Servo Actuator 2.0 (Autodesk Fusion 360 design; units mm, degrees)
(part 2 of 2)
sketch "Sketch25" plane through (0, 0, 1.008) normal (0, 0, 1) x axis (-1, 0, 0)
  line L1 (-20.0076, 9.3042) -> (-16.55, 9.3042)
  line L2 (-20.0076, 2.9542) -> (-20.0076, 9.3042)
  line L3 (-16.55, 2.9542) -> (-20.0076, 2.9542)
  line L4 (-20.0076, -11.4458) -> (-17.255, -11.4458)
  line L5 (-20.0076, -17.7958) -> (-20.0076, -11.4458)
  line L6 (-17.255, -17.7958) -> (-20.0076, -17.7958)
  line L7 (-3.4928, -22.1208) -> (-13.668, -22.1208)
  line L8 (0.1537, -18.4744) -> (-3.4928, -22.1208)
  line L9 (0.1537, -10.7673) -> (0.1537, -18.4744)
  line L10 (-3.4928, -7.1208) -> (0.1537, -10.7673)
  line L11 (-13.668, -7.1208) -> (-3.4928, -7.1208)
  line L12 (-20.0076, -17.7958) -> (-17.255, -17.7958)
  line L13 (-20.0076, -11.4458) -> (-20.0076, -17.7958)
  line L14 (-17.255, -11.4458) -> (-20.0076, -11.4458)
  line L15 (-17.255, -17.7958) -> (-17.255, -11.4458)
  line L16 (-20.0076, 2.9542) -> (-16.55, 2.9542)
  line L17 (-20.0076, 9.3042) -> (-20.0076, 2.9542)
  line L18 (-16.55, 9.3042) -> (-20.0076, 9.3042)
  line L19 (-16.55, 2.9542) -> (-16.55, 9.3042)
  arc A1 centre (-8.3963, 6.1292) radius 8.75 clockwise from (-16.55, 9.3042) to (-16.55, 2.9542)
  arc A2 centre (-9.026, -14.6208) radius 8.8203 clockwise from (-17.255, -11.4458) to (-13.668, -7.1208)
  arc A3 centre (-9.026, -14.6208) radius 8.8203 clockwise from (-13.668, -22.1208) to (-17.255, -17.7958)
  point P10 (-20.0076, -11.4458)
  point P20 (-20.0076, -11.4458)
  point P12 (-17.255, -17.7958)
  point P18 (-17.255, -17.7958)
  point P5 (-20.0076, 9.3042)
  point P24 (-20.0076, 9.3042)
  point P2 (-16.55, 2.9542)
  point P22 (-16.55, 2.9542)
  horizontal L12
  vertical L13
  horizontal L14
  vertical L15
  coincident P10 P20
  coincident P12 P18
  horizontal L16
  vertical L17
  horizontal L18
  vertical L19
  coincident P5 P24
  coincident P2 P22
extrude "Extrude10" cut sketch "Sketch25" profile of L1 L2 L3 L16 L17 L18 L19 against normal blind 8.89
extrude "Extrude11" cut sketch "Sketch25" profile of L4 L5 L6 L12 L13 L14 L15 distance 11.43
copy_paste "CutPaste1"
remove_instance "RemoveInstance8"
sketch "Sketch1" plane through (0, 0, 0) normal (0, 0, 1) x axis (1, 0, 0)
  line L1 (-7.25, -8.75) -> (7.25, -8.75)
  line L2 (-7.25, 8.75) -> (-7.25, -8.75)
  line L3 (7.25, 8.75) -> (-7.25, 8.75)
  line L4 (7.25, -8.75) -> (7.25, 8.75)
  line L5 (-7.25, 8.75) -> (7.25, -8.75)
  line L6 (7.25, 8.75) -> (-7.25, -8.75)
  line L7 (0, 8.75) -> (0, -8.75)
  line L8 (-2.5, -2.35) -> (2.5, -2.35)
  line L9 (-2.5, 1.45) -> (-2.5, -2.35)
  line L10 (2.5, 1.45) -> (-2.5, 1.45)
  line L11 (2.5, -2.35) -> (2.5, 1.45)
  line L12 (-2.5, 1.45) -> (2.5, -2.35)
  line L13 (2.5, 1.45) -> (-2.5, -2.35)
  line L14 (7.25, -0.45) -> (-7.25, -0.45)
  line L15 (3.75, -8.75) -> (7.25, -5.25)
  line L16 (-3.75, -8.75) -> (-7.25, -5.25)
  arc A1 centre (0, 0.1797) radius 8.5703 clockwise from (-7.25, 4.75) to (7.25, 4.75)
  circle C1 centre (6, -0.45) radius 1.5
  circle C2 centre (-6, -0.45) radius 1.5
  point P6 (0, 0)
  point P1 (0, 0)
  point P7 (0, -8.75)
  point P8 (0, 8.75)
  point P13 (0, -0.45)
  point P14 (-7.25, -0.45)
  point P15 (7.25, -0.45)
  point P16 (7.25, 4.75)
  point P17 (-7.25, 4.75)
  point P19 (7.25, 4.75)
  point P18 (-7.25, 4.75)
  point P21 (7.25, -5.25)
  point P22 (3.75, -8.75)
  point P23 (7.25, -5.25)
  point P24 (3.75, -8.75)
  point P25 (-7.25, -5.25)
  point P26 (-3.75, -8.75)
  point P27 (6, -0.45)
  point P2 (7.25, -8.75)
  point P5 (7.25, 8.75)
  horizontal L1
  perpendicular L1 L2
  parallel L1 L3
  parallel L2 L4
  coincident L5 P6
  coincident L6 P6
  coincident P1 P6
  midpoint L1 P7
  midpoint L3 P8
  horizontal L8
  perpendicular L8 L9
  parallel L8 L10
  parallel L9 L11
  coincident L12 P13
  coincident L13 P13
  coincident L7 P13
  coincident L2 P14
  coincident L4 P15
  perpendicular L4 L14
  coincident P13 L14
  coincident L4 P16
  symmetric L7 P16 P17
  coincident P8 A1
  tangent L3 A1
  coincident P16 P19
  coincident P17 P18
  coincident L4 P21
  coincident L1 P22
  coincident P21 P23
  coincident P22 P24
  symmetric L7 P23 P25
  symmetric L7 P24 P26
  coincident L14 P27
  symmetric L7 C1 C2
  dimension "d1_4" distance P2 P5 = 17.5
  dimension "d2_4" distance L2 L4 = 14.5
  dimension "d3_4" distance L1 L8 = 6.4
  dimension "d4_4" distance L3 L10 = 7.3
  dimension "d5_4" distance L9 L11 = 5
  dimension "d6_4" distance P5 P16 = 4
  dimension "d7_4" distance P2 P21 = 3.5
  dimension "d8_4" distance P2 P22 = 3.5
  dimension "d9_4" diameter C1 = 3
  dimension "d10_4" distance L11 P27 = 3.5 (= "2 mm + 1.5 mm")
extrude "Extrude1" new body sketch "Sketch1" profile of L1 L2 L4 L8 L9 L10 L11 A1 L15 L16 C1 C2 against normal blind 1.7 named "d11_4"
extrude "Extrude2" new body sketch "Sketch1" profile of L8 L9 L10 L11 along normal blind 1.5 named "d13_4"
sketch "Sketch2" plane through (0, 0, 0) normal (0, 0, 1) x axis (-1, 0, 0)
  line L1 (3.75, 8.75) -> (7.25, 5.25)
  line L2 (-3.75, 8.75) -> (3.75, 8.75)
  line L3 (-7.25, 5.25) -> (-3.75, 8.75)
  line L4 (-7.25, 1.2792) -> (-7.25, 5.25)
  line L5 (-7.25, -4.75) -> (-7.25, -0.3792)
  line L6 (7.25, -0.3792) -> (7.25, -4.75)
  line L7 (7.25, 5.25) -> (7.25, 1.2792)
  line L8 (2.5, -1.45) -> (-2.5, -1.45)
  line L9 (2.5, 2.35) -> (2.5, -1.45)
  line L10 (-2.5, 2.35) -> (2.5, 2.35)
  line L11 (-2.5, -1.45) -> (-2.5, 2.35)
  line L12 (2.5, 2.35) -> (-2.5, -1.45)
  line L13 (2.5, -1.45) -> (-2.5, 2.35)
  line L14 (11.5, 11.95) -> (-11.5, 11.95)
  line L15 (11.5, -11.05) -> (11.5, 11.95)
  line L16 (-11.5, -11.05) -> (11.5, -11.05)
  line L17 (-11.5, 11.95) -> (-11.5, -11.05)
  line L18 (11.5, -11.05) -> (-11.5, 11.95)
  line L19 (-11.5, -11.05) -> (11.5, 11.95)
  line L20 (8.5, 8.95) -> (-8.5, 8.95)
  line L21 (8.5, -8.05) -> (8.5, 8.95)
  line L22 (-8.5, -8.05) -> (8.5, -8.05)
  line L23 (-8.5, 8.95) -> (-8.5, -8.05)
  line L24 (8.5, -8.05) -> (-8.5, 8.95)
  line L25 (-8.5, -8.05) -> (8.5, 8.95)
  arc A1 centre (-6, 0.45) radius 1.5 clockwise from (-7.25, 1.2792) to (-7.25, -0.3792)
  arc A2 centre (0, -0.1797) radius 8.5703 clockwise from (7.25, -4.75) to (-7.25, -4.75)
  arc A3 centre (6, 0.45) radius 1.5 clockwise from (7.25, -0.3792) to (7.25, 1.2792)
  circle C1 centre (-8.5, 8.95) radius 1.5
  point P15 (-2.5, -1.45)
  point P19 (-2.5, -1.45)
  point P17 (2.5, 2.35)
  point P20 (2.5, 2.35)
  point P18 (-2.5, 2.35)
  point P21 (-2.5, 2.35)
  point P16 (2.5, -1.45)
  point P22 (2.5, -1.45)
  point P27 (0, 0.45)
  point P32 (0, 0.45)
  point P28 (-8.5, 8.95)
  point P33 (-8.5, 8.95)
  point P25 (11.5, -11.05)
  point P26 (-11.5, -11.05)
  point P24 (11.5, 11.95)
  point P29 (8.5, 8.95)
  point P31 (-8.5, -8.05)
  coincident P15 P19
  coincident P17 P20
  coincident P18 P21
  coincident P16 P22
  horizontal L14
  perpendicular L14 L15
  parallel L14 L16
  parallel L15 L17
  coincident L18 P27
  coincident L19 P27
  midpoint L12 P27
  horizontal L20
  perpendicular L20 L21
  parallel L20 L22
  parallel L21 L23
  coincident L24 P32
  coincident L25 P32
  coincident P27 P32
  coincident P28 P33
  dimension "d15_3" distance P25 P26 = 23
  dimension "d16_3" distance P24 P25 = 23
  dimension "d21_3" distance P28 P29 = 17
  dimension "d22_1" distance P28 P31 = 17
  dimension "d23_1" diameter C1 = 3
extrude "Extrude3" add sketch "Sketch2" profile of L1 L2 L3 L4 A1 L5 A2 L6 A3 L7 L8 L9 L10 L11 L14 L15 L16 L17 against normal blind 1.7 named "d17_3"
fillet "Fillet1" radius 3 named "d20_3"
extrude "Extrude4" cut sketch "Sketch2" profile of C1 against normal blind 5 named "d24_1"
work_axis "WorkAxis1" sketch "Sketch2"
circular_pattern "C-Pattern1" TotalAngle 360 named "d27_1"
copy_paste "CutPaste7"
copy_paste_bodies "CopyPasteBodies1"
component_from_bodies "Body->Comp2"
copy_paste "CutPaste1"
sketch "Sketch26" plane through (0, 0, 3.1168) normal (0, 0, 1) x axis (-1, 0, 0)
  line L1 (-17.255, -17.7958) -> (-17.255, -11.4458)
  line L2 (-3.4928, -22.1208) -> (-13.668, -22.1208)
  line L3 (0.1537, -18.4744) -> (-3.4928, -22.1208)
  line L4 (0.1537, -10.7673) -> (0.1537, -18.4744)
  line L5 (-3.4928, -7.1208) -> (0.1537, -10.7673)
  line L6 (-13.668, -7.1208) -> (-3.4928, -7.1208)
  line L7 (-10.2963, -17.1208) -> (-10.2963, -12.1208)
  line L8 (-6.4963, -17.1208) -> (-10.2963, -17.1208)
  line L9 (-6.4963, -12.1208) -> (-6.4963, -17.1208)
  line L10 (-10.2963, -12.1208) -> (-6.4963, -12.1208)
  line L11 (-6.4963, -12.1208) -> (-10.2963, -17.1208)
  line L12 (-10.2963, -12.1208) -> (-6.4963, -17.1208)
  line L13 (6.8437, -26.1208) -> (-23.6363, -26.1208)
  line L14 (6.8437, -3.1208) -> (6.8437, -26.1208)
  line L15 (-23.6363, -3.1208) -> (6.8437, -3.1208)
  line L16 (-23.6363, -26.1208) -> (-23.6363, -3.1208)
  line L17 (6.8437, -3.1208) -> (-23.6363, -26.1208)
  line L18 (-23.6363, -3.1208) -> (6.8437, -26.1208)
  line L19 (-23.8863, -26.3708) -> (-23.8863, -2.8708)
  line L20 (7.0937, -26.3708) -> (-23.8863, -26.3708)
  line L21 (7.0937, -2.8708) -> (7.0937, -26.3708)
  line L22 (-23.8863, -2.8708) -> (7.0937, -2.8708)
  line L23 (-3.6338, -9.3883) -> (-13.1588, -9.3883)
  line L24 (-3.6338, 21.6466) -> (-3.6338, -9.3883)
  line L25 (-13.1588, 21.6466) -> (-3.6338, 21.6466)
  line L26 (-13.1588, -9.3883) -> (-13.1588, 21.6466)
  line L27 (-3.6338, 21.6466) -> (-13.1588, -9.3883)
  line L28 (-13.1588, 21.6466) -> (-3.6338, -9.3883)
  line L29 (-2.7026, -22.1208) -> (-4.2901, -22.1208)
  line L30 (-2.7026, -36.2208) -> (-2.7026, -22.1208)
  line L31 (-4.2901, -36.2208) -> (-2.7026, -36.2208)
  line L32 (-4.2901, -22.1208) -> (-4.2901, -36.2208)
  line L33 (-2.7026, -36.2208) -> (-4.2901, -22.1208)
  line L34 (-4.2901, -36.2208) -> (-2.7026, -22.1208)
  line L35 (-12.5026, -24.395) -> (-14.0901, -24.395)
  line L36 (-12.5026, -33.9467) -> (-12.5026, -24.395)
  line L37 (-14.0901, -33.9467) -> (-12.5026, -33.9467)
  line L38 (-14.0901, -24.395) -> (-14.0901, -33.9467)
  line L39 (-12.5026, -33.9467) -> (-14.0901, -24.395)
  line L40 (-14.0901, -33.9467) -> (-12.5026, -24.395)
  arc A1 centre (-9.026, -14.6208) radius 8.8203 clockwise from (-13.668, -22.1208) to (-17.255, -17.7958)
  arc A2 centre (-9.026, -14.6208) radius 8.8203 clockwise from (-17.255, -11.4458) to (-13.668, -7.1208)
  circle C1 centre (-3.4963, -29.1708) radius 2.2
  arc A3 centre (-8.3963, 6.1292) radius 8.75 clockwise from (-16.55, 9.3042) to (-16.55, 2.9542)
  circle C2 centre (-13.2963, -29.1708) radius 2.2
  point P12 (-10.2963, -17.1208)
  point P15 (-10.2963, -17.1208)
  point P14 (-6.4963, -12.1208)
  point P16 (-6.4963, -12.1208)
  point P13 (-6.4963, -17.1208)
  point P17 (-6.4963, -17.1208)
  point P11 (-10.2963, -12.1208)
  point P18 (-10.2963, -12.1208)
  point P19 (-8.3963, -14.6208)
  point P24 (-8.3963, -14.6208)
  point P37 (-8.3963, 6.1292)
  point P32 (-8.3963, 6.1292)
  point P38 (-4.2901, -22.1208)
  point P42 (-3.4963, -29.1708)
  point P25 (-3.4963, -29.1708)
  point P48 (-13.2963, -29.1708)
  point P43 (-13.2963, -29.1708)
  point P21 (6.8437, -26.1208)
  point P22 (6.8437, -3.1208)
  point P20 (-23.6363, -26.1208)
  point P33 (-13.1588, -9.3883)
  point P34 (-3.6338, -9.3883)
  point P46 (-12.5026, -33.9467)
  point P47 (-14.0901, -33.9467)
  point P40 (-2.7026, -36.2208)
  point P41 (-4.2901, -36.2208)
  coincident P12 P15
  coincident P14 P16
  coincident P13 P17
  coincident P11 P18
  midpoint L12 P19
  horizontal L13
  perpendicular L13 L14
  parallel L13 L15
  parallel L14 L16
  coincident L17 P24
  coincident L18 P24
  coincident P19 P24
  horizontal L23
  perpendicular L23 L24
  parallel L23 L25
  parallel L24 L26
  coincident L27 P37
  coincident L28 P37
  coincident P32 P37
  horizontal L29
  perpendicular L29 L30
  parallel L29 L31
  parallel L30 L32
  coincident L2 P38
  coincident L33 P42
  coincident L34 P42
  coincident P25 P42
  horizontal L35
  perpendicular L35 L36
  parallel L35 L37
  parallel L36 L38
  coincident L39 P48
  coincident L40 P48
  coincident P43 P48
  dimension "d229" distance P21 P22 = 23
  dimension "d230" distance P20 P21 = 30.48
  dimension "d231" = 0.25
  dimension "d232" distance P33 P34 = 9.525
  dimension "d235" distance P46 P47 = 1.5875 (= "( 1 / 16 ) * 1 in")
  dimension "d236" distance P40 P41 = 1.5875 (= "( 1 / 16 ) * 1 in")
extrude "Extrude1" cut sketch "Sketch26" profile of L1 A1 L2 L3 L4 L5 L6 A2 C1 L19 L20 L21 L22 A3 L23 L24 L26 L29 L30 L32 C2 L35 L36 L38 along normal blind 11.43
position "Position9"
extrude "Extrude2" add of existing geometry blind 11.938
copy_paste "CutPaste1"
copy_paste "CutPaste2"
sketch "Sketch27" plane through (0, 0, 8.3168) normal (0, 0, 1) x axis (-1, 0, 0)
  line L1 (-1.5476, 25.3604) -> (3.2149, 20.5979)
  line L2 (-15.2451, 25.3604) -> (-1.5476, 25.3604)
  line L3 (-20.0076, 20.5979) -> (-15.2451, 25.3604)
  line L4 (-20.0076, 9.3042) -> (-20.0076, 20.5979)
  line L5 (-16.55, 9.3042) -> (-20.0076, 9.3042)
  line L6 (-20.0076, 2.9542) -> (-16.55, 2.9542)
  line L7 (-20.0076, -11.4458) -> (-20.0076, 2.9542)
  line L8 (-17.255, -11.4458) -> (-20.0076, -11.4458)
  line L9 (0.1537, -10.7673) -> (-3.4928, -7.1208)
  line L10 (0.1537, -18.4744) -> (0.1537, -10.7673)
  line L11 (-3.4928, -22.1208) -> (0.1537, -18.4744)
  line L12 (-20.0076, -17.7958) -> (-17.255, -17.7958)
  line L13 (-20.0076, -29.3396) -> (-20.0076, -17.7958)
  line L14 (-15.2451, -34.1021) -> (-20.0076, -29.3396)
  line L15 (-1.5476, -34.1021) -> (-15.2451, -34.1021)
  line L16 (3.2149, -29.3396) -> (-1.5476, -34.1021)
  line L17 (3.2149, 20.5979) -> (3.2149, -29.3396)
  line L18 (-16.55, 2.9542) -> (-16.55, 9.3042)
  line L19 (10.3682, 15.8479) -> (-27.1608, 15.8479)
  line L20 (10.3682, -3.5896) -> (10.3682, 15.8479)
  line L21 (-27.1608, -3.5896) -> (10.3682, -3.5896)
  line L22 (-27.1608, 15.8479) -> (-27.1608, -3.5896)
  line L23 (10.3682, -3.5896) -> (-27.1608, 15.8479)
  line L24 (-27.1608, -3.5896) -> (10.3682, 15.8479)
  line L25 (-22.7793, 18.2292) -> (-24.2215, 18.2292)
  line L26 (-8.8375, 18.2292) -> (-22.7793, 18.2292)
  arc A1 centre (-8.3963, 6.1292) radius 8.75 clockwise from (-16.55, 9.3042) to (-16.55, 2.9542)
  arc A2 centre (-9.026, -14.6208) radius 8.8203 clockwise from (-17.255, -11.4458) to (-13.668, -7.1208)
  arc A3 centre (-8.5804, -15.3408) radius 9.6671 clockwise from (-13.668, -7.1208) to (-3.4928, -7.1208)
  arc A4 centre (-8.5804, -13.9008) radius 9.6671 clockwise from (-3.4928, -22.1208) to (-13.668, -22.1208)
  arc A5 centre (-9.026, -14.6208) radius 8.8203 clockwise from (-13.668, -22.1208) to (-17.255, -17.7958)
  circle C1 centre (-13.2963, 20.4292) radius 2.2
  circle C2 centre (-13.2963, -29.1708) radius 2.2
  circle C3 centre (-3.4963, 20.4292) radius 2.2
  circle C4 centre (-3.4963, -29.1708) radius 2.2
  arc A6 centre (-8.3963, 6.1292) radius 8.75 clockwise from (-16.55, 9.3042) to (-16.55, 2.9542)
  circle C5 centre (-13.2963, 20.4292) radius 2.2
  point P39 (-8.3963, 6.1292)
  point P34 (-8.3963, 6.1292)
  horizontal L19
  perpendicular L19 L20
  parallel L19 L21
  parallel L20 L22
  coincident L23 P39
  coincident L24 P39
  coincident P34 P39
  perpendicular L4 L25
  perpendicular L4 L26
  tangent C1 L26
  dimension "d239" distance L19 L26 = 2.3813 (= "( 3 / 32 ) * 1 in")
extrude "Extrude12" cut sketch "Sketch27" profile of L4 L5 A1 L6 L7 L17 L18 L19 L21 L22 against normal blind 7.3152
extrude "Extrude13" add of existing geometry blind 2.7525
extrude "Extrude14" add of existing geometry blind 7.62
sketch "Sketch28" plane through (0, 0, 8.3168) normal (0, 0, 1) x axis (-1, 0, 0)
  line L1 (-13.1588, -1.2112) -> (-13.1588, -2.8708)
  line L2 (-20.0076, 2.9542) -> (-16.55, 2.9542)
  line L3 (-20.0076, -2.8708) -> (-20.0076, 2.9542)
  line L4 (-13.1588, -2.8708) -> (-20.0076, -2.8708)
  line L5 (-27.1608, -3.5896) -> (10.3682, -3.5896)
  line L6 (-27.1608, 15.8479) -> (-27.1608, -3.5896)
  line L7 (10.3682, -3.5896) -> (10.3682, 15.8479)
  line L8 (10.3682, 15.8479) -> (-27.1608, 15.8479)
  arc A1 centre (-8.3963, 6.1292) radius 8.75 clockwise from (-13.1588, -1.2112) to (-16.55, 2.9542)
extrude "Extrude3" cut sketch "Sketch28" against normal blind 7.3152
extrude "Extrude4" add of existing geometry blind 7.62
move "Move1"
move "Move1"
extrude "Extrude5" cut of existing geometry blind -0.3036 (= "-( 0.105700787401575 in - ( ( 3 / 32 ) * 1 in ) )")
extrude "Extrude6" add of existing geometry blind 3.175
extrude "Extrude7" add of existing geometry blind 3.175
position "Position10"
sketch "Sketch29" plane through (0, 0, -2.477) normal (0, 0, 1) x axis (-1, 0, 0)
  line L1 (-20.0076, -3.5896) -> (-20.0076, 15.8479)
  line L2 (3.2149, -3.5896) -> (-20.0076, -3.5896)
  line L3 (3.2149, 15.8479) -> (3.2149, -3.5896)
  line L4 (-20.0076, 15.8479) -> (3.2149, 15.8479)
  line L5 (0.8337, 15.8479) -> (3.2149, 15.8479)
  line L6 (0.8337, -3.5896) -> (0.8337, 15.8479)
  line L7 (3.2149, -3.5896) -> (0.8337, -3.5896)
  line L8 (3.2149, 15.8479) -> (3.2149, -3.5896)
  point P8 (0.8337, -3.5896)
  point P5 (3.2149, 15.8479)
  point P6 (3.2149, 15.8479)
  horizontal L5
  vertical L6
  horizontal L7
  vertical L8
  coincident L2 P8
  coincident P5 P6
  dimension "d256" distance L6 L8 = 2.3813 (= "( 3 / 32 ) * 1 in")
extrude "Extrude8" add sketch "Sketch29" profile of L2 L3 L4 L5 L6 L7 L8 along normal blind 10.795
extrude "Extrude9" cut of existing geometry blind -0.0012 (= "-4.921E-05 in")
extrude "Extrude10" cut of existing geometry blind -0.4572
extrude "Extrude11" cut of existing geometry blind -0.25
extrude "Extrude15" add of existing geometry blind 3.175
work_plane "WorkPlane6" AlongDistance -3.175
split "Split1"
remove_body "RemoveBody1"
remove_body "RemoveBody2"
extrude "Extrude12" new body of existing geometry blind 3.175
combine "Combine1"
extrude "Extrude16" add sketch "Sketch29" profile of L2 L3 L4 L5 L6 L7 L8 along normal blind 7.62
extrude "Extrude17" cut of existing geometry blind -0.0012 (= "-4.921E-05 in")
extrude "Extrude19" add of existing geometry blind 2
sketch "Sketch30" plane through (0, 0, 3.1168) normal (0, 0, 1) x axis (-1, 0, 0)
  line L1 (0.1537, -18.4744) -> (-3.4928, -22.1208)
  line L2 (0.1537, -10.7673) -> (0.1537, -18.4744)
  line L3 (-3.4928, -7.1208) -> (0.1537, -10.7673)
  line L4 (-20.0076, -11.4458) -> (-17.255, -11.4458)
  line L5 (-20.0076, -17.7958) -> (-20.0076, -11.4458)
  line L6 (-17.255, -17.7958) -> (-20.0076, -17.7958)
  line L7 (-20.0076, -17.7958) -> (-17.255, -17.7958)
  line L8 (-17.255, -11.4458) -> (-20.0076, -11.4458)
  line L9 (-12.5772, -11.4458) -> (-20.0076, -11.4458)
  line L10 (-12.5772, -17.7958) -> (-12.5772, -11.4458)
  line L11 (-20.0076, -17.7958) -> (-12.5772, -17.7958)
  line L12 (-20.0076, -11.4458) -> (-20.0076, -17.7958)
  line L13 (-3.4928, -22.1208) -> (-13.668, -22.1208)
  line L14 (-13.668, -7.1208) -> (-3.4928, -7.1208)
  arc A1 centre (-9.026, -14.6208) radius 8.8203 clockwise from (-13.668, -22.1208) to (-17.255, -17.7958)
  arc A2 centre (-9.026, -14.6208) radius 8.8203 clockwise from (-17.255, -11.4458) to (-13.668, -7.1208)
  point P15 (-20.0076, -11.4458)
  point P17 (-20.0076, -11.4458)
  point P13 (-17.255, -17.7958)
  horizontal L9
  vertical L10
  horizontal L11
  vertical L12
  coincident P15 P17
  coincident P13 L11
extrude "Extrude2" cut sketch "Sketch30" profile of L4 L5 L6 L7 L8 L9 L10 L11 L12 along normal blind 4.7625
extrude "Extrude20" cut of existing geometry blind -1.1906 (= "( -3 / 64 ) * 1 in")
sketch "Sketch31" plane through (0, 0, -2.1734) normal (0, 0, 1) x axis (-1, 0, 0)
  line L1 (-20.0076, 15.8479) -> (2.0243, 15.8479)
  line L2 (-20.0076, -3.5896) -> (-20.0076, 15.8479)
  line L3 (2.0243, -3.5896) -> (-20.0076, -3.5896)
  line L4 (2.0243, 15.8479) -> (2.0243, -3.5896)
  line L5 (-18.8169, -3.5896) -> (-20.0076, -3.5896)
  line L6 (-18.8169, 15.8479) -> (-18.8169, -3.5896)
  line L7 (-20.0076, 15.8479) -> (-18.8169, 15.8479)
  line L8 (-20.0076, -3.5896) -> (-20.0076, 15.8479)
  line L9 (-18.8169, 15.8479) -> (-20.0076, -3.5896)
  line L10 (-18.8169, -3.5896) -> (-20.0076, 15.8479)
  line L11 (-11.6624, 9.3042) -> (-27.1621, 9.3042)
  line L12 (-11.6624, 2.9542) -> (-11.6624, 9.3042)
  line L13 (-27.1621, 2.9542) -> (-11.6624, 2.9542)
  line L14 (-27.1621, 9.3042) -> (-27.1621, 2.9542)
  line L15 (-11.6624, 2.9542) -> (-27.1621, 9.3042)
  line L16 (-27.1621, 2.9542) -> (-11.6624, 9.3042)
  point P8 (-18.8169, 15.8479)
  point P4 (-20.0076, -3.5896)
  point P6 (-20.0076, -3.5896)
  point P10 (-20.0076, -3.5896)
  point P3 (-20.0076, 15.8479)
  point P11 (-20.0076, 15.8479)
  point P12 (-19.4122, 6.1292)
  point P17 (-19.4122, 6.1292)
  point P13 (-27.1621, 9.3042)
  point P16 (-27.1621, 2.9542)
  horizontal L5
  vertical L6
  horizontal L7
  vertical L8
  coincident L1 P8
  coincident P4 P6
  coincident P4 P10
  coincident P3 P11
  coincident L10 P12
  coincident L9 P12
  horizontal L11
  perpendicular L11 L12
  parallel L11 L13
  parallel L12 L14
  coincident L15 P17
  coincident L16 P17
  coincident P12 P17
  dimension "d282" distance L6 L8 = 1.1906 (= "( 3 / 64 ) * 1 in")
  dimension "d283" distance P13 P16 = 6.35
extrude "Extrude21" add sketch "Sketch31" profile of L1 L2 L3 L5 L6 L7 L8 L11 L13 along normal blind 7.3152
extrude "Extrude12" cut of existing geometry blind -1.1906 (= "( -3 / 64 ) * 1 in")
extrude "Extrude22" cut of existing geometry blind -0.3036 (= "( ( 3 / 32 ) * 1 in ) - 0.105700787401575 in")
extrude "Extrude13" add sketch "Sketch31" profile of L1 L2 L3 L5 L6 L7 L8 L11 L13 along normal blind 7.3152 and against normal blind 1.27
extrude "Extrude14" cut of existing geometry blind -0.7112
remove_instance "RemoveInstance3"
remove_instance "RemoveInstance1"
split "Split1"
split "Split2"
remove_body "RemoveBody1"
combine "Combine2"
offset_faces "OffsetFaces1" distance -0.5
move_face "MoveFace2"
move "Move1"
sketch "Sketch32" plane through (0, 0, 28) normal (0, 0, 1) x axis (-1, 0, 0)
  line L1 (-17.6263, 14.8742) -> (-17.6263, -23.6158)
  line L2 (0.8337, 14.8742) -> (-17.6263, 14.8742)
  line L3 (0.8337, -23.6158) -> (0.8337, 14.8742)
  line L4 (-17.6263, -23.6158) -> (0.8337, -23.6158)
  line L5 (-20.0076, -29.3396) -> (-20.0076, 20.5979)
  line L6 (-15.2451, -34.1021) -> (-20.0076, -29.3396)
  line L7 (-1.5476, -34.1021) -> (-15.2451, -34.1021)
  line L8 (3.2149, -29.3396) -> (-1.5476, -34.1021)
  line L9 (3.2149, 20.5979) -> (3.2149, -29.3396)
  line L10 (-1.5476, 25.3604) -> (3.2149, 20.5979)
  line L11 (-15.2451, 25.3604) -> (-1.5476, 25.3604)
  line L12 (-20.0076, 20.5979) -> (-15.2451, 25.3604)
  circle C1 centre (-13.2963, -29.1708) radius 1.7
  circle C2 centre (-3.4963, -29.1708) radius 1.7
  circle C3 centre (-3.4963, 20.4292) radius 1.7
  circle C4 centre (-13.2963, 20.4292) radius 1.7
  circle C5 centre (-30.0348, -20.1562) radius 4
  circle C6 centre (-30.0348, -20.1562) radius 7
  concentric C5 C6
  dimension "d298" diameter C5 = 8
  dimension "d299" diameter C6 = 14
extrude "Extrude13" new body sketch "Sketch32" profile of C5 C6 along normal blind 7
align "Align2"
split "Split1"
copy_paste_bodies "CutPasteBodies3"
sketch "Sketch34" plane through (0, 0, 26.3456) normal (0, 0, -1) x axis (1, 0, 0)
  circle C1 centre (8.3963, -14.6208) radius 3.175
extrude "Extrude1" cut sketch "Sketch34" against normal blind 8.95 (magnitude of "-15.3 mm + 6.35 mm")
extrude "Extrude6" cut of existing geometry blind -2.5908
extrude "Extrude1" add of existing geometry blind 0.9906
extrude "Extrude3" add of existing geometry blind 2.9769 (= "0.0234488188976379 in + ( ( 3 / 32 ) * 1 in )")
extrude "Extrude4" cut of existing geometry blind -2.9769 (= "-( 0.0234488188976379 in + ( ( 3 / 32 ) * 1 in ) )")
position "Position11"
move "Move1"
extrude "Extrude2" cut of existing geometry blind 2.2769 (= "0.0384586614173229 in + 1.3 mm")
align "Align1"
extrude "Extrude3" cut of existing geometry blind -2.286
extrude "Extrude4" add of existing geometry blind 1.0922
extrude "Extrude7" add of existing geometry blind 1.8796
align "Align3"
extrude "Extrude5" add of existing geometry blind 0.7937 (= "( 1 / 32 ) * 1 in")
extrude "Extrude6" cut of existing geometry blind -0.7937 (= "( -1 / 32 ) * 1 in")
move "Move2"
extrude "Extrude8" cut of existing geometry blind -0.7937 (= "( -1 / 32 ) * 1 in")
extrude "Extrude5" add of existing geometry blind 0.7937 (= "( 1 / 32 ) * 1 in")
align "Align2"
extrude "Extrude6" add of existing geometry blind 0.7937 (= "( 1 / 32 ) * 1 in")
extrude "Extrude7" add of existing geometry blind 2.0066
extrude "Extrude23" add of existing geometry blind 4.445 (= "0.30 in - 0.125 in")
extrude "Extrude2" cut of existing geometry blind -4.1402
component_from_bodies "Body->Comp3"
copy_paste "CutPaste8"
sketch "Sketch35" plane through (-3.2149, 0, 0) normal (-1, 0, 0) x axis (0, -1, 0)
  line L1 (-11.4458, 5.1418) -> (-11.4458, 7.8793)
  line L2 (20.5979, 5.1418) -> (-11.4458, 5.1418)
  line L3 (20.5979, 28) -> (20.5979, 5.1418)
  line L4 (-29.3396, 28) -> (20.5979, 28)
  line L5 (-29.3396, 5.1418) -> (-29.3396, 28)
  line L6 (-17.7958, 5.1418) -> (-29.3396, 5.1418)
  line L7 (-17.7958, 7.8793) -> (-17.7958, 5.1418)
  line L8 (-11.4458, 7.8793) -> (-17.7958, 7.8793)
  line L9 (-7.6208, 17.8125) -> (-21.6208, 17.8125)
  line L10 (-7.6208, 24.8125) -> (-21.6208, 24.8125)
  line L11 (-21.6208, 17.8125) -> (-7.6208, 24.8125)
  line L12 (-21.6208, 24.8125) -> (-7.6208, 17.8125)
  circle C1 centre (-14.6208, 21.3125) radius 3.5
  point P13 (-7.6208, 24.8125)
  point P14 (-7.6208, 24.8125)
  point P10 (-21.6208, 17.8125)
  point P15 (-21.6208, 17.8125)
  point P11 (-7.6208, 17.8125)
  point P16 (-7.6208, 17.8125)
  point P12 (-21.6208, 24.8125)
  point P17 (-21.6208, 24.8125)
  point P18 (-14.6208, 21.3125)
  coincident P13 P14
  coincident P10 P15
  coincident P11 P16
  coincident P12 P17
  midpoint L11 P18
  dimension "d336" diameter C1 = 7
sketch "Sketch37" plane through (0, 0, 17.8125) normal (0, 0, 1) x axis (-1, 0, 0)
  line L1 (0.0837, 3.7223) -> (0.0837, -22.8658)
  line L2 (-16.8763, -22.8658) -> (-16.8763, 3.7223)
  line L3 (0.0837, -22.8658) -> (-16.8763, -22.8658)
  circle C1 centre (-8.3963, -14.6208) radius 8
  arc A1 centre (-8.3963, 5.8792) radius 8.75 clockwise from (0.0837, 3.7223) to (-16.8763, 3.7223)
  circle C2 centre (-8.3963, -14.6208) radius 8
  circle C3 centre (-8.3963, -14.6208) radius 7
  circle C4 centre (-8.3963, -14.6208) radius 7
  circle C5 centre (-8.3963, -14.6208) radius 7.2
  dimension "d345" = 0.2
extrude "Extrude14" new body sketch "Sketch37" profile of C1 L1 A1 L2 L3 C2 C5 along normal blind 8.5875
combine "Combine3"
extrude "Extrude11" cut sketch "Sketch35" profile of C1 against normal blind 35.56
sketch "Sketch38" plane through (-0.8337, 0, 0) normal (1, 0, 0) x axis (0, 1, 0)
  line L1 (-14.8742, 28) -> (23.6158, 28)
  line L2 (-14.8742, 26.4) -> (-14.8742, 28)
  line L3 (23.6158, 26.4) -> (-14.8742, 26.4)
  line L4 (23.6158, 28) -> (23.6158, 26.4)
  line L5 (18.1208, 17.8125) -> (11.1208, 17.8125)
  line L6 (18.1208, 24.8125) -> (18.1208, 17.8125)
  line L7 (11.1208, 24.8125) -> (18.1208, 24.8125)
  line L8 (11.1208, 17.8125) -> (11.1208, 24.8125)
  line L9 (18.1208, 24.8125) -> (11.1208, 17.8125)
  line L10 (11.1208, 24.8125) -> (18.1208, 17.8125)
  line L11 (22.6208, 17.8125) -> (14.6208, 17.8125)
  line L12 (21.8208, 17.8125) -> (14.6208, 17.8125)
  line L13 (18.1208, 24.8125) -> (11.1208, 24.8125)
  line L14 (18.1208, 30.6305) -> (18.1208, 24.8125)
  line L15 (11.1208, 30.6305) -> (18.1208, 30.6305)
  line L16 (11.1208, 24.8125) -> (11.1208, 30.6305)
  circle C1 centre (14.6208, 21.3125) radius 3.5
  point P11 (14.6208, 21.3125)
  point P6 (14.6208, 21.3125)
  point P14 (21.8208, 17.8125)
  point P9 (18.1208, 24.8125)
  point P7 (11.1208, 17.8125)
  point P8 (18.1208, 17.8125)
  horizontal L5
  perpendicular L5 L6
  parallel L5 L7
  parallel L6 L8
  coincident L9 P11
  coincident L10 P11
  coincident P6 P11
  coincident L5 P14
  horizontal L13
  vertical L14
  horizontal L15
  vertical L16
  coincident P9 L14
  dimension "d358" distance P7 P8 = 7
extrude "Extrude12" cut sketch "Sketch38" profile of L1 L3 C1 L5 L6 L7 L8 L11 L12 L13 L14 L15 L16 along normal blind 18.46
extrude "Extrude8" add of existing geometry blind 0.5 (= "0.5 * ( 0.1018700787401575 in - ( ( 1 / 16 ) * 1 in ) )")
extrude "Extrude9" add of existing geometry blind 0.5 (= "0.5 * ( 0.1018700787401575 in - ( ( 1 / 16 ) * 1 in ) )")
work_plane "WorkPlane8" RotateAngle 0
sketch "Sketch39" plane through (4.3963, 14.6208, 18.5259) normal (-1, 0, 0) x axis (0, 1, 0)
  circle C1 centre (0, -2.7866) radius 3.5
  circle C2 centre (0, -2.7866) radius 2
  concentric C1 C2
  dimension "d366" diameter C2 = 4
extrude "Extrude10" cut sketch "Sketch39" profile of C2 against normal blind 1.5
extrude "Extrude9" add of existing geometry blind 0.125 (= "0.25 mm / 2")
extrude "Extrude10" add of existing geometry blind 0.125 (= "0.25 mm / 2")
extrude "Extrude11" add of existing geometry blind 2.032
sketch "Sketch40" plane through (0, 0, 24.8191) normal (0, 0, 1) x axis (-1, 0, 0)
  line L1 (-7.6026, -12.7708) -> (-7.6026, -16.4708)
  line L2 (-9.1901, -12.7708) -> (-7.6026, -12.7708)
  line L3 (-9.1901, -16.4708) -> (-9.1901, -12.7708)
  line L4 (-7.6026, -16.4708) -> (-9.1901, -16.4708)
  line L5 (-7.3526, -12.5208) -> (-7.3526, -16.7208)
  line L6 (-9.4401, -12.5208) -> (-7.3526, -12.5208)
  line L7 (-9.4401, -16.7208) -> (-9.4401, -12.5208)
  line L8 (-7.3526, -16.7208) -> (-9.4401, -16.7208)
  circle C1 centre (-8.3963, -14.6208) radius 4
  dimension "d375" = 0.25
extrude "Extrude12" cut sketch "Sketch40" profile of L1 L2 L3 L4 L5 L6 L7 L8 against normal blind 12.0142
delete_face "DeleteFace8"
delete_face "DeleteFace9"
delete_face "DeleteFace5"
delete_face "DeleteFace6"
delete_face "DeleteFace10"
delete_face "DeleteFace7"
delete_face "DeleteFace11"
delete_face "DeleteFace8"
fillet "Fillet2" radius 3.175
sketch "Sketch41" plane through (0, 0, 1.968) normal (0, 0, 1) x axis (-1, 0, 0)
  line L1 (-20.0076, 9.0542) -> (-18.8169, 9.0542)
  line L2 (-20.0076, 2.7042) -> (-20.0076, 9.0542)
  line L3 (-18.8169, 2.7042) -> (-20.0076, 2.7042)
  line L4 (-18.8169, -3.8396) -> (-18.8169, 2.7042)
  line L5 (2.0243, -3.8396) -> (-18.8169, -3.8396)
  line L6 (2.0243, 15.5979) -> (2.0243, -3.8396)
  line L7 (-18.8169, 15.5979) -> (2.0243, 15.5979)
  line L8 (-18.8169, 9.0542) -> (-18.8169, 15.5979)
  line L9 (-12.9401, 2.7042) -> (-20.0076, 2.7042)
  line L10 (-12.9401, 9.0542) -> (-12.9401, 2.7042)
  line L11 (-20.0076, 9.0542) -> (-12.9401, 9.0542)
  line L12 (-20.0076, 2.7042) -> (-20.0076, 9.0542)
  circle C1 centre (-8.3963, 5.8792) radius 8.75
  circle C2 centre (-8.3963, 5.8792) radius 8.75
  point P4 (-20.0076, 2.7042)
  point P11 (-20.0076, 2.7042)
  point P3 (-20.0076, 9.0542)
  point P14 (-20.0076, 9.0542)
  horizontal L9
  vertical L10
  horizontal L11
  vertical L12
  coincident P4 P11
  coincident P3 P14
extrude "Extrude24" add sketch "Sketch41" profile of L4 L5 L6 L7 L8 C1 C2 L9 L11 along normal blind 3.1738
extrude "Extrude13" cut of existing geometry blind -1
extrude "Extrude13" add of existing geometry blind 2.7375
as_built_joint "As-built2"
remove_instance "RemoveInstance3"
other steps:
base_feature "Base Feature1"
base_feature "Base Feature1"
base_feature "Base Feature1"
base_feature "Base Feature1"
base_feature "Base Feature1"
base_feature "Base Feature1"
base_feature "Base Feature1"
base_feature "Base Feature1"
base_feature "Base Feature1"
base_feature "Base Feature2"
move "Move1"
base_feature "Base Feature1"
base_feature "Base Feature3"
move "Move2"
base_feature "Base Feature2"
base_feature "Base Feature2"
move "Move1"
base_feature "Base Feature4"
base_feature "Base Feature3"
move "Move2"
base_feature "Base Feature1"
delete_face "DeleteFace5"
delete_face "DeleteFace6"
delete_face "DeleteFace7"
offset_faces "OffsetFaces1" distance -3.175
chamfer "Chamfer1" distance 4.7625
move_face "MoveFace1"
base_feature "Base Feature1"
fillet "Fillet1" radius 3.175
create_component "CreateComponent1"
create_component "CreateComponent2"
create_component "CreateComponent1"
create_component "CreateComponent1"
create_component "CreateComponent2"
create_component "CreateComponent2"
remove_body "RemoveBody1"
remove_body "RemoveBody1"
remove_body "RemoveBody2"
create_component "CreateComponent3"
remove_body "RemoveBody1"
create_component "CreateComponent3"
remove_body "RemoveBody3"
remove_instance "RemoveInstance1"
create_component "CreateComponent4"
remove_instance "RemoveInstance2"
remove_body "RemoveBody1"
remove_body "RemoveBody4"
create_component "CreateComponent1"
remove_body "RemoveBody2"
remove_body "RemoveBody3"
remove_body "RemoveBody4"
remove_body "RemoveBody6"
remove_instance "RemoveInstance1"
remove_body "RemoveBody7"
remove_body "RemoveBody9"
remove_instance "RemoveInstance1"
remove_body "RemoveBody5"
remove_body "RemoveBody6"
remove_body "RemoveBody1"
remove_body "RemoveBody2"
create_component "CreateComponent5"
remove_instance "RemoveInstance3"
create_component "CreateComponent1"
create_component "CreateComponent2"
create_component "CreateComponent3"
create_component "CreateComponent4"
create_component "CreateComponent5"
create_component "CreateComponent6"
create_component "CreateComponent6"
remove_instance "RemoveInstance1"
create_component "CreateComponent1"
remove_body "RemoveBody5"
create_component "CreateComponent2"
remove_body "RemoveBody6"
create_component "CreateComponent3"
remove_body "RemoveBody7"
create_component "CreateComponent7"
remove_instance "RemoveInstance5"
remove_instance "RemoveInstance2"
create_component "CreateComponent26"
remove_instance "RemoveInstance9"
create_component "CreateComponent27"
remove_body "RemoveBody10"
remove_instance "RemoveInstance10"
create_component "CreateComponent28"
remove_instance "RemoveInstance11"
remove_instance "RemoveInstance12"
remove_body "RemoveBody11"
remove_body "RemoveBody1"
create_component "CreateComponent48"
remove_body "RemoveBody13"
remove_instance "RemoveInstance13"
remove_body "RemoveBody14"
